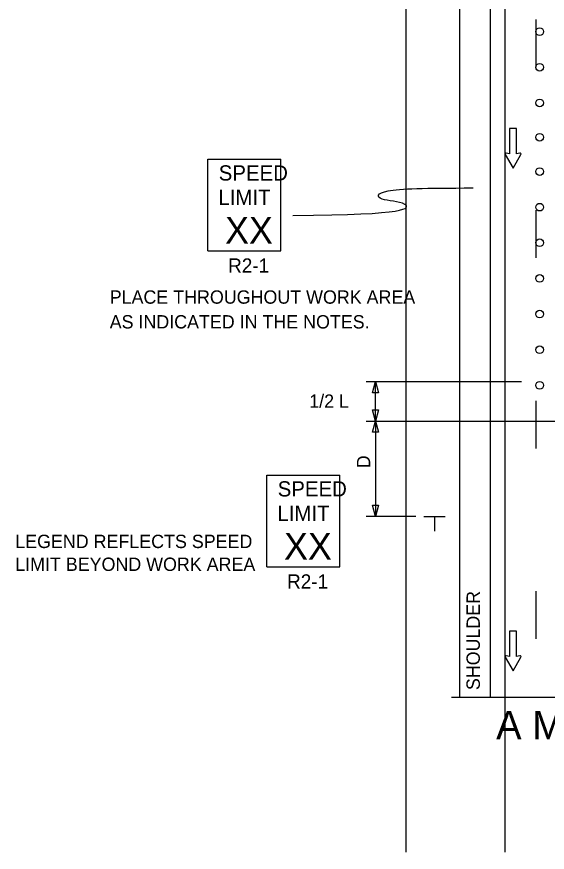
# Model space of a CAD drawing. Extents: x 16473 to 19504, y 4850 to 6919.
# Drawn here: x 16741.3 to 17019.4, y 6067.7 to 6506.2 of the extents above; entities that cross this region are included whole.
import ezdxf

# ---------------------------------------------------------------- set-up
doc = ezdxf.new("R2010")
doc.units = 0
for name, color, linetype in [('ALI_LEGAL_EX', 7, 'Continuous'), ('MT_SCRATCH_LEVEL_E', 7, 'Continuous'), ('PAVT_EDGE_EX', 7, 'Continuous'), ('TRAFFIC_SIGNS_PR', 7, 'Continuous'), ('TYPICAL_TEXT_DIMEN_PR', 7, 'Continuous')]:
    doc.layers.add(name, color=color, linetype=linetype)

msp = doc.modelspace()

# ---------------------------------------------------------------- linework, layer by layer
at = {"layer": 'ALI_LEGAL_EX'}
for p, q in [((16945.19, 6918.86), (16945.19, 6067.75)), ((16997.19, 6918.86), (16997.19, 6067.75))]:
    msp.add_line(p, q, dxfattribs=at)
for points in [[(17013.43, 6504.69), (17013.43, 6479.69)], [(17013.43, 6404.69), (17013.43, 6379.69)], [(17013.43, 6304.69), (17013.43, 6279.69)], [(17013.43, 6204.69), (17013.43, 6179.69)]]:
    msp.add_lwpolyline(points, dxfattribs=at)
at = {"layer": 'MT_SCRATCH_LEVEL_E'}
for p, q in [((17003.35, 6447.55), (16999.61, 6447.55)), ((16999.61, 6447.55), (16999.61, 6434.29)), ((17003.35, 6447.55), (16999.61, 6447.55)), ((16999.61, 6447.55), (16999.61, 6434.29)), ((17003.35, 6434.29), (17003.35, 6447.55)), ((17003.35, 6434.29), (17003.35, 6447.55)), ((16997.35, 6433.92), (17001.5, 6426.68)), ((16997.35, 6433.92), (17001.5, 6426.68)), ((16999.61, 6434.29), (16997.83, 6434.61)), ((16999.61, 6434.29), (16997.83, 6434.61)), ((17001.5, 6426.68), (17005.61, 6433.92)), ((17001.5, 6426.68), (17005.61, 6433.92)), ((17005.13, 6434.61), (17003.35, 6434.29)), ((17005.13, 6434.61), (17003.35, 6434.29)), ((17003.35, 6183.78), (16999.61, 6183.78)), ((16999.61, 6183.78), (16999.61, 6170.52)), ((17003.35, 6183.78), (16999.61, 6183.78)), ((16999.61, 6183.78), (16999.61, 6170.52)), ((17003.35, 6170.52), (17003.35, 6183.78)), ((17003.35, 6170.52), (17003.35, 6183.78)), ((16997.35, 6170.15), (17001.5, 6162.91)), ((16997.35, 6170.15), (17001.5, 6162.91)), ((16999.61, 6170.52), (16997.83, 6170.84)), ((16999.61, 6170.52), (16997.83, 6170.84)), ((17001.5, 6162.91), (17005.61, 6170.15)), ((17001.5, 6162.91), (17005.61, 6170.15)), ((17005.13, 6170.84), (17003.35, 6170.52)), ((17005.13, 6170.84), (17003.35, 6170.52))]:
    msp.add_line(p, q, dxfattribs=at)
for centre, start, end in [((16997.76, 6434.15), 80.0362, 209.7731), ((16997.76, 6434.15), 80.0362, 209.7731), ((17005.2, 6434.15), 330.4248, 99.9638), ((17005.2, 6434.15), 330.4248, 99.9638), ((16997.76, 6170.37), 80.0362, 209.7731), ((16997.76, 6170.37), 80.0362, 209.7731), ((17005.2, 6170.38), 330.4248, 99.9638), ((17005.2, 6170.38), 330.4248, 99.9638)]:
    msp.add_arc(centre, 0.463, start, end, dxfattribs=at)
at = {"layer": 'PAVT_EDGE_EX'}
for p, q in [((16973.43, 6873.99), (16973.43, 6149.2)), ((16989.43, 6873.99), (16989.43, 6149.2))]:
    msp.add_line(p, q, dxfattribs=at)
at = {"layer": 'TRAFFIC_SIGNS_PR'}
for p, q in [((16841.41, 6431.36), (16879.81, 6431.36)), ((16841.41, 6383.36), (16841.41, 6431.36)), ((16879.81, 6383.36), (16879.81, 6431.36)), ((16841.41, 6383.36), (16879.81, 6383.36)), ((16872.31, 6265.59), (16910.71, 6265.59)), ((16872.31, 6217.59), (16872.31, 6265.59)), ((16910.71, 6217.59), (16910.71, 6265.59)), ((16872.31, 6217.59), (16910.71, 6217.59))]:
    msp.add_line(p, q, dxfattribs=at)
for centre in [(17015.43, 6498.35), (17015.43, 6479.66), (17015.43, 6460.96), (17015.43, 6442.96), (17015.43, 6424.96), (17015.43, 6406.26), (17015.43, 6387.57), (17015.43, 6368.87), (17015.43, 6350.17), (17015.43, 6331.47), (17015.43, 6312.78)]:
    msp.add_circle(centre, 2, dxfattribs=at)
at = {"layer": 'TYPICAL_TEXT_DIMEN_PR'}
for p, q in [((16924.43, 6314.78), (17005.97, 6314.78)), ((16927.86, 6308.91), (16929.43, 6314.78)), ((16929.43, 6294.02), (16929.43, 6314.78)), ((16929.43, 6314.78), (16931, 6308.91)), ((16929.43, 6308.91), (16927.86, 6308.91)), ((16931, 6308.91), (16929.43, 6308.91)), ((16929.43, 6294.02), (16927.86, 6299.88)), ((16927.86, 6299.88), (16929.43, 6299.88)), ((16929.43, 6299.88), (16931, 6299.88)), ((16931, 6299.88), (16929.43, 6294.02)), ((16924.43, 6294.02), (17029.97, 6294.02)), ((16927.86, 6288.15), (16929.43, 6294.02)), ((16929.43, 6294.02), (16931, 6288.15)), ((16929.43, 6294.02), (16929.43, 6246.02)), ((16929.43, 6294.02), (16929.43, 6244.02)), ((16929.43, 6288.15), (16927.86, 6288.15)), ((16931, 6288.15), (16929.43, 6288.15)), ((16929.43, 6244.02), (16927.86, 6249.88)), ((16927.86, 6249.88), (16929.43, 6249.88)), ((16929.43, 6249.88), (16931, 6249.88)), ((16931, 6249.88), (16929.43, 6244.02)), ((16950.43, 6244.02), (16924.43, 6244.02)), ((16954.68, 6244.02), (16965.93, 6244.02)), ((16960.31, 6244.02), (16960.31, 6236.23)), ((16969.13, 6149.2), (17109.73, 6149.2))]:
    msp.add_line(p, q, dxfattribs=at)
msp.add_open_spline([(16886.05, 6401.88), (16947.69, 6402.24), (16947.69, 6409.49), (16929.81, 6409.49), (16929.81, 6415.76), (16954.82, 6416.28), (16980.54, 6416.33)], degree=3, dxfattribs=at)

# ---------------------------------------------------------------- texts
at = {"layer": 'TRAFFIC_SIGNS_PR'}
for s, height, p in [('SPEED', 8, (16847.17, 6420.22)), ('LIMIT', 8, (16847.01, 6407.42)), ('XX', 14.031, (16850.52, 6387.12)), ('R2-1', 7.44, (16852.08, 6371.92)), ('PLACE THROUGHOUT WORK AREA', 7, (16790.01, 6355.6)), ('AS INDICATED IN THE NOTES.', 7, (16790.01, 6342.6)), ('SPEED', 8, (16878.08, 6254.45)), ('LIMIT', 8, (16877.92, 6241.65)), ('XX', 14.031, (16881.43, 6221.34)), ('R2-1', 7.44, (16882.99, 6206.15))]:
    msp.add_text(s, height=height, dxfattribs=at).set_placement(p)
at = {"layer": 'TYPICAL_TEXT_DIMEN_PR'}
for s, height, p in [('1/2 L', 7, (16894.63, 6300.99)), ('LEGEND REFLECTS SPEED', 7, (16740.48, 6227.38)), ('LIMIT BEYOND WORK AREA', 7, (16740.48, 6215.38)), ('A MATCH A', 15, (16992.6, 6126.96))]:
    msp.add_text(s, height=height, dxfattribs=at).set_placement(p)
for s, p in [('D', (16926.61, 6269.24)), ('SHOULDER', (16984.08, 6152.85))]:
    msp.add_text(s, height=7, rotation=90, dxfattribs=at).set_placement(p)

doc.saveas('drawing.dxf')
